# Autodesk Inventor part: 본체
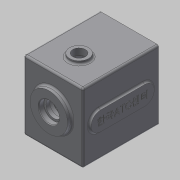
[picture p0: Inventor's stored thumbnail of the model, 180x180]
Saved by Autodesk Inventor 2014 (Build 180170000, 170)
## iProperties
Created: 2016-02
Part Number: 본체
Material: 일반
Document SubType Name: Modeling
Designer: mduedu
Density: 1 g/cm^3
Appearance: Default
Mass: 559.381 g
Surface Area: 1077.08 cm^2
Volume: 559.381 cm^3
Author: mduedu
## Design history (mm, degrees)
sketch "스케치1"
  geometry: L1 (-47, -47)-(47, -47); L2 (47, -47)-(47, 63); L3 (47, 63)-(-47, 63); L4 (-47, 63)-(-47, -47); 2 further points
  constraints: 8 end point, 2 parallel, 1 horizontal, 1 midpoint, 1 perpendicular, 1 vertical alignment
  dimensions: "d0" = 94 distance of L2.end L3.end; "d155" = 110 distance of L1.end L2.end; "d156" = 47 distance from line of L1 point (0, 0)
extrude "돌출1" new body sketch "스케치1" distance "d2" = 120; taper "d3" = 0 deg
sketch "스케치3"
  geometry: L1 (47, -47)-(-47, -47) reference; L2 (47, 63)-(47, -47) reference; L3 (-47, 63)-(47, 63) reference; L4 (-47, -47)-(-47, 63) reference; L5 (37, 53)-(37, -37); L6 (37, -37)-(-37, -37); L7 (-37, -37)-(-37, 53); L8 (-37, 53)-(37, 53); 1 further point
  constraints: 8 end point, 3 other
  dimensions: "d226" = 10 distance between parallel lines of L8 L3
extrude "돌출3" cut sketch "스케치3" distance "d11" = 110; taper "d12" = 0 deg
sketch "스케치4"
  geometry: C1 r 21 at (0, 11); 1 further point
  constraints: 1 centre point, 1 vertical alignment
  dimensions: "d13" = 21 radius of C1; "d227" = 11 distance of point (0, 0) C1.centre
extrude "돌출4" join sketch "스케치4" distance "d16" = 7; taper "d17" = 0 deg
sketch "스케치5"
  geometry: C1 r 15 at (0, -20); 1 further point
  constraints: 1 centre point, 1 vertical alignment
  dimensions: "d18" = 15 radius of C1; "d20" = 20 distance of point (0, 0) C1.centre
extrude "돌출5" join sketch "스케치5" distance "d21" = 7; taper "d22" = 0 deg
sketch "스케치6"
  geometry: C1 r 30 at (0, 11); A1 r 21 centre (0, 11) between (8.978, -7.984) and (-8.978, -7.984) reference; 1 further point
  constraints: 1 centre point, 1 coincident
  dimensions: "d228" = 60 diameter of C1
extrude "돌출6" join sketch "스케치6" distance "d25" = 7; taper "d26" = -3 deg
hole "구멍1" diameter "d29" = 35; stored, may be unused: countersink angle "d33" = 90 deg, drill point angle "d35" = 0 deg; dims "d27" = 10, "d28" = 10, "d30" = 6, "d31" = 4, "d32" = 2, "d34" = 10
hole "구멍2" diameter "d38" = 22; stored, may be unused: countersink angle "d42" = 90 deg, drill point angle "d44" = 0 deg; dims "d36" = 10, "d37" = 10, "d39" = 6, "d40" = 4, "d41" = 2, "d43" = 7
hole "구멍3" diameter "d47" = 19; stored, may be unused: countersink angle "d51" = 90 deg, drill point angle "d53" = 0 deg; dims "d45" = 10, "d46" = 10, "d48" = 6, "d49" = 4, "d50" = 2, "d52" = 1
hole "구멍4" diameter "d56" = 32; stored, may be unused: countersink angle "d60" = 90 deg, drill point angle "d62" = 0 deg; dims "d57" = 6, "d58" = 4, "d59" = 2, "d61" = 8, "d220" = 10, "d221" = 10
hole "구멍5" diameter "d65" = 25; stored, may be unused: countersink angle "d69" = 90 deg, drill point angle "d71" = 0 deg; dims "d63" = 10, "d64" = 10, "d66" = 6, "d67" = 4, "d68" = 2, "d70" = 8
fillet "모깎기2" dims "d73" = 0.3
fillet "모깎기3" dims "d74" = 2
chamfer "모따기1" distance "d75" = 1; stored, may be unused: second distance "d76" = 2, angle "d77" = 45 deg
fillet "모깎기4" dims "d78" = 3
fillet "모깎기23" dims "d240" = 1
fillet "모깎기20" dims "d229" = 3
sketch "스케치23"
  geometry: L1 (-37, 53)-(37, 53) reference; L2 (37, 53)-(37, -37) reference; L3 (37, -37)-(-37, -37) reference; L4 (-37, -37)-(-37, 53) reference; L5 (44, -47)-(-44, -47) reference; L6 (47, 60)-(47, -44) reference; L7 (-44, 63)-(44, 63) reference; L8 (-47, -44)-(-47, 60) reference; C1 r 10 at (-37, 53); C2 r 10 at (37, 53); C3 r 10 at (-37, -37); C4 r 10 at (37, -37); A1 r 3 centre (-44, -44) between (-47, -44) and (-44, -47) reference; A2 r 3 centre (44, -44) between (44, -47) and (47, -44) reference; A3 r 3 centre (44, 60) between (47, 60) and (44, 63) reference; A4 r 3 centre (-44, 60) between (-44, 63) and (-47, 60) reference; 1 further point
  constraints: 4 centre point, 4 coincident, 3 equal radius
  dimensions: "d230" = 20 diameter of C1
extrude "돌출22" join sketch "스케치23" stored distance "d235" = 10; taper "d236" = 0 deg
fillet "모깎기21" dims "d237" = 3
node "작업 평면1"
fillet "모깎기22" dims "d239" = 1
sketch "스케치12"
  geometry: A1 r 10 centre (-37, 53) between (-34.692, 43.27) and (-27.27, 50.692) reference; A2 r 10 centre (37, 53) between (27.27, 50.692) and (34.692, 43.27) reference; A3 r 10 centre (37, -37) between (34.692, -27.27) and (27.27, -34.692) reference; A4 r 10 centre (-37, -37) between (-27.27, -34.692) and (-34.692, -27.27) reference; 5 further points
  constraints: 4 coincident
hole "구멍6" sketch "스케치12" at (-37, 53), (37, 53), (37, -37), (-37, -37) diameter "d122" = 3.242; stored, may be unused: countersink angle "d126" = 90 deg, drill point angle "d128" = 120 deg; dims "d123" = 7, "d124" = 4, "d125" = 2, "d127" = 9
sketch "스케치20"
  geometry: L1 (44, 0)-(-44, 0) reference; L2 (44, -120)-(-44, -120) reference; L3 (0, 0)-(0, -120); L4 (-44, -120)-(-44, 0) reference; L5 (44, 0)-(44, -120) reference; C1 r 10 at (0, -79)
  constraints: 2 end point, 1 centre point, 1 midpoint, 1 point on line
  dimensions: "d189" = 20 diameter of C1; "d190" = 41 distance from line of C1.centre L2
extrude "돌출19" cut sketch "스케치20" stored distance "d191" = 10; taper "d192" = 0 deg
sketch "스케치18"
  geometry: C1 r 15 at (0, -79); C2 r 10 at (0, -79) reference; 1 further point
  constraints: 1 centre point, 1 concentric
  dimensions: "d174" = 30 diameter of C1
extrude "돌출17" join sketch "스케치18" distance "d175" = 5; taper "d176" = 0 deg
fillet "모깎기16" dims "d177" = 3
sketch "스케치19"
  geometry: C1 r 15 at (24.351, 79); C2 r 10 at (24.351, 79) reference; 1 further point
  constraints: 1 centre point, 1 concentric
  dimensions: "d178" = 30 diameter of C1
extrude "돌출18" cut sketch "스케치19" distance "d181" = 5; taper "d182" = 0 deg
chamfer "모따기5" distance "d183" = 1; stored, may be unused: second distance "d184" = 2, angle "d185" = 45 deg
fillet "모깎기24" dims "d242" = 3, "d243" = 3
sketch "스케치24"
  geometry: L1 (-95, 67)-(-25, 67); L2 (-25, 67)-(-25, 37); L3 (-25, 37)-(-95, 37); L4 (-95, 37)-(-95, 67); L5 (0, 0)-(0, 104) reference; L6 (-95, 52)-(-25, 52); L7 (-60, 67)-(-60, 37); A1 r 15 centre (-95, 52) between (-95, 37) and (-95, 67); A2 r 15 centre (-25, 52) between (-25, 67) and (-25, 37); A3 r 15 centre (-25, 52) between (-25, 37) and (-25, 67); A4 r 15 centre (-95, 52) between (-95, 67) and (-95, 37); 2 further points
  constraints: 12 end point, 8 point on circle, 5 midpoint, 4 centre point, 2 parallel, 2 perpendicular, 1 horizontal, 1 horizontal alignment
  dimensions: "d244" = 60 distance between parallel lines of L7 L5; "d245" = 100 dimension on A2 A1; "d246" = 30 distance between parallel lines of L3 L1
extrude "돌출23" join sketch "스케치24" distance "d247" = 3; taper "d248" = 0 deg
fillet "모깎기25" dims "d249" = 3
sketch "스케치25"
  geometry: L1 (-25, 67)-(-95, 67) reference; L2 (-95, 37)-(-25, 37) reference; A1 r 15 centre (-95, 52) between (-95, 67) and (-95, 37) reference; A2 r 15 centre (-25, 52) between (-25, 37) and (-25, 67) reference; 3 further points
  constraints: 1 horizontal alignment, 1 midpoint, 1 vertical alignment, 1 other
feature "엠보싱3" sketch "스케치25" dims "d250" = 0.5, "d251" = 0
sketch "스케치26"
  geometry: L1 (14.367, 127)-(73.633, 127) reference; L2 (0, 0)-(88, 0) reference; L3 (88, 120)-(0, 120) reference; 5 further points
  constraints: 3 vertical alignment, 2 midpoint
  dimensions: "d252" = 35 distance from line of point (44, 35) L2; "d253" = 35 distance from line of point (44, 85) L3; "d254" = 50 distance of point (44, 35) point (44, 85) (derived)
hole "구멍8" sketch "스케치26" at (44, 85), (44, 35) diameter "d255" = 6.647; stored, may be unused: countersink angle "d259" = 90 deg, drill point angle "d261" = 118 deg; dims "d256" = 6, "d257" = 4, "d258" = 2, "d260" = 8
node "솔리드1"
node "투영된 루프1"
node "투영된 루프4"
node "투영된 루프5"
node "투영된 루프6"
